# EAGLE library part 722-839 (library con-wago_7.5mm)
Serie 722, Federleiste mit abgewinkelten Einlötstiften / Series 722, Female connector with angled solder pins Polzahl / Pole No.: 9 Rastermaß / Pitch: 7.5 mm Bemessungsspannung / Rated Voltage: 630 V Nennstrom / Nominal Current: 12 A Lötstiftlänge: / Solder Pin Length: 5 mm Farbe / Color: lichtgrau / light gray Stand: 01.01.2012. Die jeweils aktuellen Daten zu diesem Artikel finden Sie in unserem Produktkatalog, den Sie unter www.wago.com einsehen können. As of: 01/01/2012. Please find the newest data for this article in our product catalogue, which can be viewed under www.wago.com.
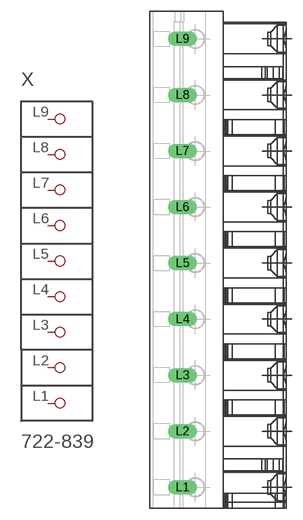
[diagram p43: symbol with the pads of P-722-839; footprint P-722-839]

Designator prefix X

## 722-839  [P-722-839]
L1  P1
L2  P2
L3  P3
L4  P4
L5  P5
L6  P6
L7  P7
L8  P8
L9  P9

## Footprint P-722-839 (pad centres in mm)
drill 1.3 long: L1 -5.078,-30.45; L2 -5.078,-22.95; L3 -5.078,-15.45; L4 -5.078,-7.95; L5 -5.078,-0.45; L6 -5.078,7.05; L7 -5.078,14.55; L8 -5.078,22.05; L9 -5.078,29.55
